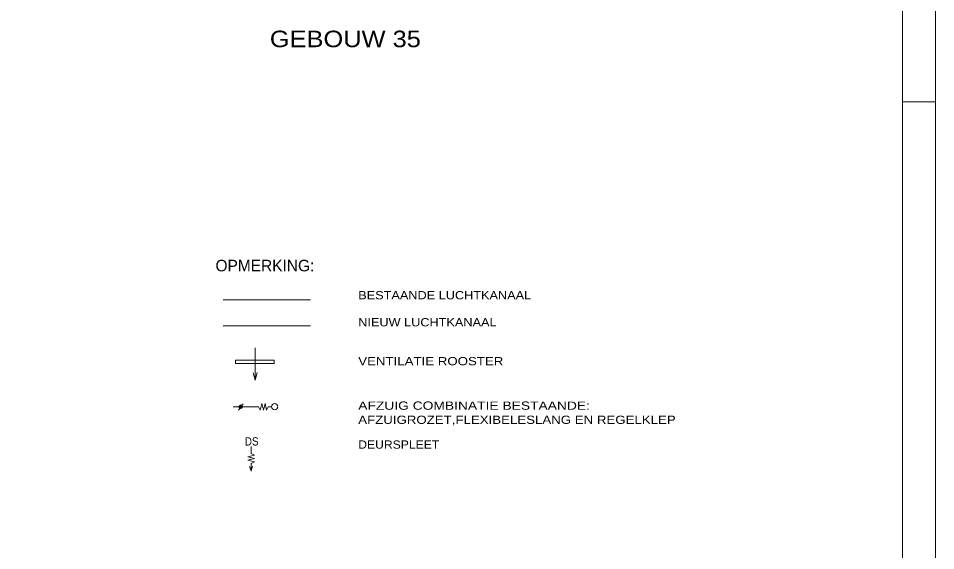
# Model space of a CAD drawing. Extents: x 295824 to 414724, y 24924 to 109024.
# Drawn here: x 386960 to 414724, y 41038 to 57152 of the extents above; entities that cross this region are included whole.
import ezdxf

# ---------------------------------------------------------------- set-up
doc = ezdxf.new("R2010")
doc.units = 0
doc.header["$LTSCALE"] = 100
for name, color, linetype, lineweight in [('1', 7, 'Continuous', 13), ('16', 7, 'Continuous', 13), ('24', 7, 'Continuous', 13)]:
    doc.layers.add(name, color=color, linetype=linetype, lineweight=lineweight)

msp = doc.modelspace()

# ---------------------------------------------------------------- hatches: boundary and pattern name
at = {"layer": '24'}
msp.add_hatch(color=256, dxfattribs=at).paths.add_polyline_path([(393690.5, 45341.2, 1), (393690.5, 45449.8, 1)])

# ---------------------------------------------------------------- linework, layer by layer
at = {"layer": '1'}
for p, q in [((414723.6, 24923.8), (414723.6, 109023.8)), ((413723.6, 54623.8), (414723.6, 54623.8))]:
    msp.add_line(p, q, dxfattribs=at)
msp.add_lwpolyline([(304995.6, 25923.8), (413723.6, 25923.8), (413723.6, 108023.8), (304995.6, 108023.8)], dxfattribs=at)
at = {"layer": '24'}
for p, q in [((393159.7, 48635.2), (395801.2, 48635.2)), ((393159.7, 47848.4), (395801.2, 47848.4)), ((394127.4, 46197.6), (394067.8, 46420)), ((394175.9, 45395.5), (393457.7, 45395.5)), ((393761.4, 45487.1), (393619.7, 45295.5)), ((394002.3, 43449.5), (394047.3, 43593.7)), ((393959.9, 43585.3), (394002.3, 43449.5))]:
    msp.add_line(p, q, dxfattribs=at)
for points in [[(394127.4, 47172.6), (394127.4, 46197.6), (394189, 46427.8)], [(394625.9, 45395.5), (394525.9, 45395.5), (394475.9, 45295.5), (394425.9, 45495.5), (394375.9, 45295.5), (394325.9, 45495.5), (394275.9, 45295.5), (394225.9, 45395.5), (394175.9, 45395.5)], [(394005.7, 43443.6), (394005.7, 43674.9), (394105.7, 43724.9), (393905.7, 43774.9), (394105.7, 43824.9), (393905.7, 43874.9), (394105.7, 43924.9), (394005.7, 43974.9), (394005.7, 44193.6)]]:
    msp.add_lwpolyline(points, dxfattribs=at)
msp.add_lwpolyline([(393536, 46701.7), (394702, 46701.7), (394702, 46801.7), (393536, 46801.7)], close=True, dxfattribs=at)
for centre, radius in [((393690.5, 45395.5), 54.3), ((394717.6, 45395.5), 95)]:
    msp.add_circle(centre, radius, dxfattribs=at)

# ---------------------------------------------------------------- texts
at = {"layer": '16'}
msp.add_text('OPMERKING:', height=350, dxfattribs=at).set_placement((392927.8, 49492.6))
for s, width, p in [('BESTAANDE LUCHTKANAAL', 1.15, (397247.5, 48645.4)), ('NIEUW LUCHTKANAAL', 1.15, (397247.5, 47827.2)), ('VENTILATIE ROOSTER', 1.2, (397247.5, 46649.2)), ('AFZUIG COMBINATIE BESTAANDE: ', 1.25, (397247.5, 45302.8)), ('AFZUIGROZET,FLEXIBELESLANG EN REGELKLEP', 1.2, (397247.5, 44874.5)), ('DEURSPLEET', 1.1, (397247.5, 44124.8))]:
    msp.add_text(s, height=250, dxfattribs=dict(at, width=width)).set_placement(p)
at = {"layer": '24'}
for s, height, width, p in [('GEBOUW 35', 500, 1.15, (394571.2, 56278.7)), ('DS', 250, 0.9, (393814.2, 44220.7))]:
    msp.add_text(s, height=height, dxfattribs=dict(at, width=width)).set_placement(p)

doc.saveas('drawing.dxf')
